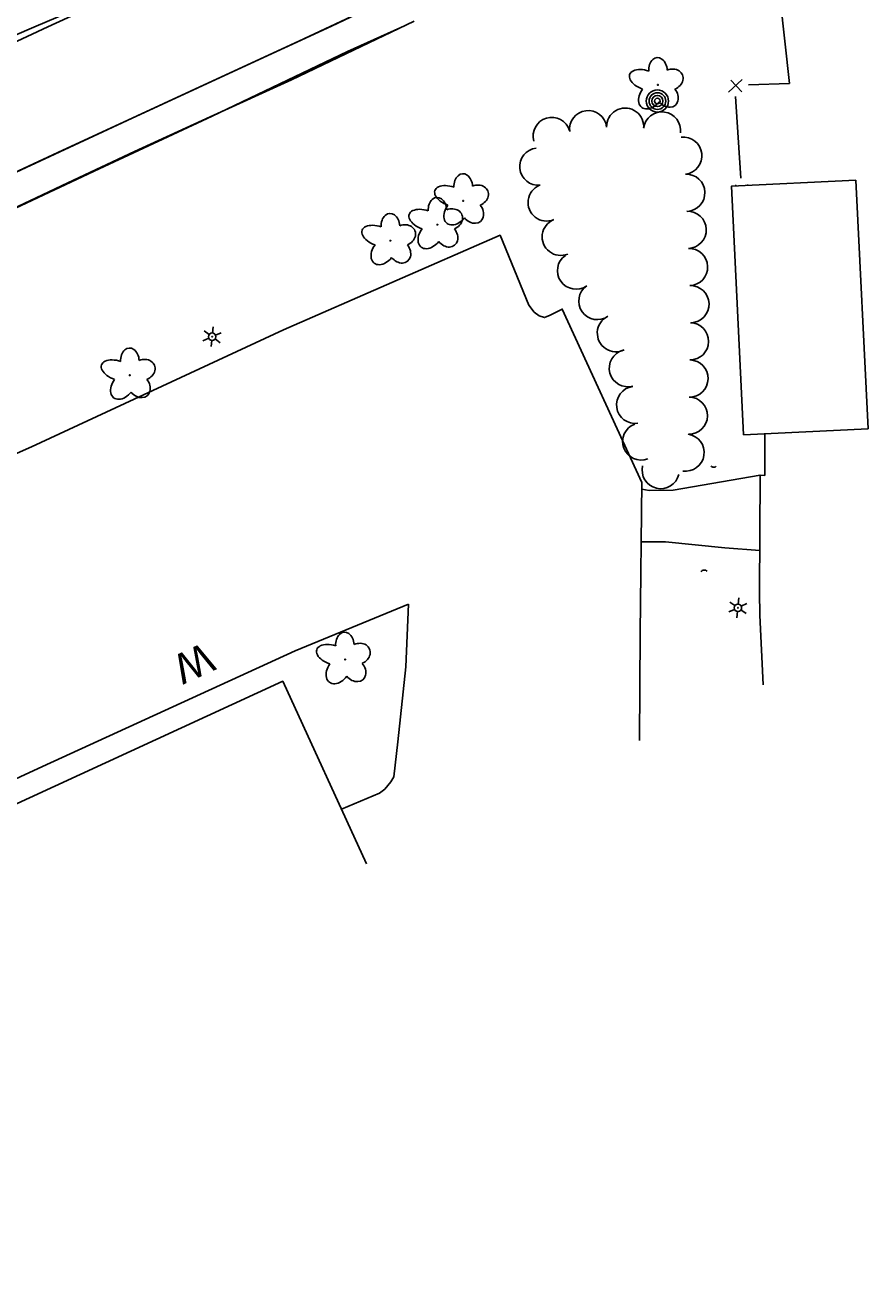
# Model space of a CAD drawing. Extents: x 588843 to 2552415, y 180129 to 269402.
# Drawn here: x 593050.1 to 593218.9, y 187647.9 to 187898.4 of the extents above; entities that cross this region are included whole.
import ezdxf

# ---------------------------------------------------------------- set-up
doc = ezdxf.new("R2010")
doc.units = 0
for name, color, linetype in [('Default', 7, 'Continuous'), ('E_BLD', 7, 'Continuous'), ('E_DRN', 7, 'Continuous'), ('E_DWY', 7, 'Continuous'), ('E_FEN_P', 7, 'Continuous'), ('E_LAND_TreeLine_P', 7, 'Continuous'), ('E_LAND_Vegetation', 7, 'Continuous'), ('E_LTG', 7, 'Continuous'), ('E_MISCPROP', 7, 'Continuous'), ('E_PATH_Sidewalk', 7, 'Continuous'), ('E_RDWY', 7, 'Continuous'), ('E_RDWY_Gravel', 7, 'Continuous'), ('E_WAL', 7, 'Continuous'), ('E_WAL_Text', 7, 'Continuous'), ('Level 11', 7, 'Continuous')]:
    doc.layers.add(name, color=color, linetype=linetype)

# ---------------------------------------------------------------- blocks, each defined once
blk = doc.blocks.new('W_34')
at = {"layer": 'E_WAL_Text'}
blk.add_text('W', height=12, dxfattribs=at).set_placement((-4.46, -6))
blk = doc.blocks.new('DTRE')
at = {"layer": 'Default'}
blk.add_circle((-0.18, 0), 0.183, dxfattribs=at)
for centre, major_axis, ratio in [((-1.87, 5.32), (1.36, -4.98), 0.782863), ((4.06, 2.74), (-5.27, -2.93), 0.691916), ((-5.87, 0.15), (4.93, -0.12), 0.832022), ((-2.49, -5.24), (1.8, 4.86), 0.716896), ((3.54, -3.71), (-5.01, 4.58), 0.560249)]:
    blk.add_ellipse(centre, major_axis=major_axis, ratio=ratio, start_param=1.570796, end_param=4.712389, dxfattribs=at)
blk = doc.blocks.new('LPOL')
at = {"layer": 'Default'}
for p, q in [((-4, 0), (-1.5, 0)), ((-0.75, 1.3), (-2, 3.46)), ((0.75, 1.3), (2, 3.46)), ((1.5, 0), (4, 0)), ((-2, -3.46), (-0.75, -1.3)), ((2, -3.46), (0.75, -1.3))]:
    blk.add_line(p, q, dxfattribs=at)
for radius in [1.5, 1.5, 1.5, 0.125]:
    blk.add_circle((0, 0), radius, dxfattribs=at)
blk = doc.blocks.new('POLE')
at = {"layer": 'Default'}
for radius in [4.46, 3.35, 2.23, 1.12]:
    blk.add_circle((0, 0), radius, dxfattribs=at)
blk = doc.blocks.new('CULV2')
at = {"layer": 'E_DRN'}
blk.add_arc((19.7, 14.8), 24.6, 216.8699, 323.1301, dxfattribs=at)

msp = doc.modelspace()

# ---------------------------------------------------------------- linework, layer by layer
at = {"layer": 'E_BLD'}
msp.add_lwpolyline([(593194.04, 187816.35), (593191.58, 187866.1), (593216.48, 187867.33), (593218.94, 187817.58), (593194.04, 187816.35)], close=True, dxfattribs=at)
msp.add_lwpolyline([(592935.24, 187647.87), (592919.05, 187683.07), (593101.74, 187767.07), (593118.54, 187730.53)], dxfattribs=at)
at = {"layer": 'E_DWY'}
for points in [[(593181.14, 187923.46), (593184.66, 187923.83), (593189.86, 187923.9), (593194.99, 187923.27), (593199.32, 187921.93), (593202.92, 187919.84), (593206.32, 187917.03), (593210.26, 187912.74), (593213.53, 187907.85), (593201.33, 187903.65), (593203.21, 187886.64)], [(593173.35, 187776.67), (593173.68, 187806.81), (593157.72, 187841.53), (593155.29, 187840.3), (593154.19, 187839.84), (593153.12, 187840.16), (593152.09, 187840.95), (593151.02, 187842.31), (593145.27, 187856.3), (593101.9, 187837.37), (593051.45, 187813.95), (593008.94, 187795.22), (592967.05, 187776.14)], [(593197.29, 187780.26), (593197.22, 187784.87), (593197.33, 187808.32), (593198.28, 187808.25), (593198.31, 187816.56)], [(593126.91, 187782.51), (593126.37, 187769.92), (593124.81, 187754.97), (593123.98, 187747.91), (593123.41, 187746.97), (593122.22, 187745.5), (593121.15, 187744.64), (593113.52, 187741.44)], [(593197.29, 187780.26), (593197.93, 187766.34)], [(593173.35, 187776.67), (593173.19, 187755.19)], [(593053.66, 187749.98), (593020.41, 187734.66), (593010.98, 187729.97), (593002.27, 187726.29), (592968.07, 187711.2), (592951.89, 187703.24), (592953.5, 187698.91)]]:
    msp.add_lwpolyline(points, dxfattribs=at)
at = {"layer": 'E_FEN_P'}
for p, q in [((593193.75, 187887.49), (593190.98, 187884.93)), ((593193.69, 187885.01), (593191.48, 187887.37)), ((593192.44, 187866.4), (593192.68, 187866.16)), ((593194.92, 187866.44), (593194.74, 187866.26))]:
    msp.add_line(p, q, dxfattribs=at)
for points in [[(593203.21, 187886.64), (593195.04, 187886.39)], [(593192.39, 187884.05), (593192.94, 187875.89)], [(593192.94, 187875.89), (593193.5, 187867.73)]]:
    msp.add_lwpolyline(points, dxfattribs=at)
at = {"layer": 'E_LAND_TreeLine_P'}
for centre, start, end in [((593155.61, 187876.19), 16.5865, 196.5865), ((593162.9, 187877.53), 7.0996, 187.0996), ((593170.31, 187878.04), 1.1284, 181.1284), ((593177.7, 187877.27), 352.8385, 172.8385), ((593181.95, 187872.22), 276.8051, 96.8051), ((593152.92, 187870.04), 96.229, 276.229), ((593182.56, 187864.81), 272.1246, 92.1246), ((593154.58, 187862.86), 112.3709, 292.3709), ((593182.83, 187857.38), 272.1246, 92.1246), ((593157.41, 187855.99), 112.3709, 292.3709), ((593160.47, 187849.23), 125.0283, 305.0283), ((593183.11, 187849.95), 272.1246, 92.1246), ((593164.74, 187843.14), 125.0283, 305.0283), ((593183.39, 187842.52), 272.1246, 92.1246), ((593168.45, 187836.72), 116.5889, 296.5889), ((593183.31, 187835.08), 269.1353, 89.1353), ((593170.85, 187829.71), 105.3883, 285.3883), ((593183.2, 187827.64), 269.1353, 89.1353), ((593172.31, 187822.36), 98.1142, 278.1142), ((593183.09, 187820.21), 269.1353, 89.1353), ((593173.52, 187815.04), 110.5294, 290.5294), ((593182.41, 187812.81), 261.5714, 81.5714), ((593177.43, 187809.31), 166.6313, 346.6313)]:
    msp.add_arc(centre, 3.72, start, end, dxfattribs=at)
at = {"layer": 'E_PATH_Sidewalk'}
for points in [[(593173.67, 187805.53), (593175.14, 187805.24), (593179.9, 187805.28), (593197.33, 187808.32)], [(593197.26, 187793.21), (593190.27, 187793.73), (593178.38, 187794.95), (593173.55, 187794.97)]]:
    msp.add_lwpolyline(points, dxfattribs=at)
at = {"layer": 'E_RDWY'}
for points in [[(593069.83, 187905.59), (593052.38, 187898.15), (593034.04, 187890.27), (593011.39, 187880.66), (592992.46, 187872.46), (592978.61, 187866.54), (592960.27, 187858.66), (592943.69, 187851.7), (592926.01, 187844.16), (592910.92, 187837.64), (592890.22, 187828.71), (592874.41, 187821.87), (592858.37, 187814.91), (592842.64, 187808.2), (592838.82, 187806.55)], [(593121.8, 187902.99), (593104.99, 187895.16), (593088.6, 187887.64), (593072.61, 187880.23), (593056.69, 187872.84), (593041.99, 187866.08), (593024.02, 187857.77), (593009.55, 187851.04), (592995.73, 187844.7), (592981.11, 187837.04), (592967.7, 187830.15), (592955.72, 187823.88), (592942.29, 187817.04), (592927.27, 187809.17), (592913.95, 187802.33), (592900.96, 187795.53), (592885.31, 187787.46), (592869.76, 187779.38)]]:
    msp.add_lwpolyline(points, dxfattribs=at)
at = {"layer": 'E_RDWY_Gravel'}
msp.add_lwpolyline([(593128.07, 187899.15), (593114.38, 187892.6), (593103.51, 187887.41), (593087.2, 187880), (593072.03, 187873.05), (593058.73, 187866.79), (593044.85, 187860.27), (593026.11, 187851.86), (593010.46, 187844.34), (592991.37, 187835.53), (592981.67, 187831.21), (592969.54, 187825.5), (592960.86, 187820.99), (592962.45, 187815.07), (592948.23, 187808.31), (592939.29, 187804.33)], dxfattribs=at)
at = {"layer": 'E_WAL'}
msp.add_lwpolyline([(593126.91, 187782.51), (593104.22, 187773.15), (593053.66, 187749.98)], dxfattribs=at)
at = {"layer": 'Level 11'}
for points in [[(593081.4, 187910.28), (593054.72, 187898.04), (593032.93, 187887.88), (593004.81, 187874.85), (592982.82, 187864.63), (592962.98, 187855.52), (592937.9, 187843.87), (592916.36, 187833.91), (592892.32, 187822.84), (592869.04, 187811.99), (592843.71, 187800.23), (592817.43, 187788), (592792.4, 187776.51), (592762.63, 187762.69), (592737.11, 187750.77), (592703.8, 187735.36), (592679.17, 187724.03), (592657.28, 187713.81), (592635.69, 187703.85), (592608.86, 187691.51), (592583.03, 187679.54), (592565.01, 187672.08), (592544.46, 187665.17), (592522.46, 187657.87)], [(593122.8, 187903.55), (593111.48, 187898.12), (593091.84, 187889.08), (593070.59, 187879.27), (593045.51, 187867.6), (593019.94, 187855.78), (592999.42, 187846.23), (592979.25, 187836.83), (592959.66, 187827.79), (592938.02, 187817.78), (592914.06, 187806.58), (592893.4, 187797.07), (592871.04, 187786.65), (592849.4, 187776.63), (592826.45, 187766.09), (592803.8, 187755.51), (592782.31, 187745.59)], [(593125.42, 187897.9), (593114.68, 187893.06), (593087.58, 187880.17), (593064.96, 187869.58), (593038.1, 187857.01), (593014.72, 187846.15), (592985.55, 187832.71), (592957.75, 187820.18), (592934.13, 187809.01), (592892.81, 187789.75), (592865.94, 187777.49), (592838.35, 187764.09), (592811.6, 187751.96), (592781.25, 187737.74)]]:
    msp.add_lwpolyline(points, dxfattribs=at)

# ---------------------------------------------------------------- block references
at = {"layer": 'E_DRN'}
for p, xscale, yscale, rotation in [((593187.52, 187810.17), 0.026443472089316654, 0.026443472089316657, -3.375954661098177), ((593186.73, 187789.07), 0.03094260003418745, 0.030942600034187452, -174.75579249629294)]:
    msp.add_blockref('CULV2', p, dxfattribs=dict(at, xscale=xscale, yscale=yscale, rotation=rotation))
at = {"layer": 'E_LAND_Vegetation'}
for p, xscale, yscale, rotation in [((593176.78, 187886.36), 0.5, 0.5, -156.56674682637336), ((593137.79, 187863.14), 0.5, 0.5, -156.56674682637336), ((593132.63, 187858.39), 0.5, 0.5, -156.56674682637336), ((593123.21, 187855.19), 0.5, 0.5, -156.56674682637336), ((593071.04, 187828.26), 0.5, 0.5, -156.56674682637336), ((593114.16, 187771.38), 0.5000000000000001, 0.5000000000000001, -155.36095699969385)]:
    msp.add_blockref('DTRE', p, dxfattribs=dict(at, xscale=xscale, yscale=yscale, rotation=rotation))
at = {"layer": 'E_LTG'}
for p, xscale, yscale, rotation in [((593087.61, 187836), 0.5, 0.5, -156.56674682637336), ((593192.89, 187781.76), 0.49999999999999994, 0.49999999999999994, -155.45775611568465)]:
    msp.add_blockref('LPOL', p, dxfattribs=dict(at, xscale=xscale, yscale=yscale, rotation=rotation))
at = {"layer": 'E_MISCPROP', "xscale": 0.5, "yscale": 0.5, "rotation": -156.56674682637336}
msp.add_blockref('POLE', (593176.77, 187883.16), dxfattribs=at)
at = {"layer": 'E_WAL_Text', "xscale": 0.5000000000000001, "yscale": 0.5000000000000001, "rotation": -155.36095699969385}
msp.add_blockref('W_34', (593085.36, 187771.31), dxfattribs=at)

doc.saveas('drawing.dxf')
